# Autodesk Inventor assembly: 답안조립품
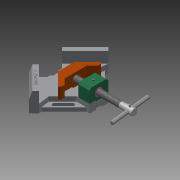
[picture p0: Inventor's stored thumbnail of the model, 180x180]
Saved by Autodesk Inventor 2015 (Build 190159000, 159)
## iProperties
Created: 2020-05
Part Number: 답안조립품
Document SubType Name: Assembly
Designer: now
Author: now
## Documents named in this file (11)
- C:\Users\now\Desktop\700506V1009\답안조립품.iam
- C:\Users\now\Desktop\700506V1009\리드스크류.ipt
- C:\Users\now\Desktop\700506V1009\멈춤나사 M4x5.ipt
- C:\Users\now\Desktop\700506V1009\멈춤나사 M4x10.ipt
- C:\Users\now\Desktop\700506V1009\본체.ipt
- C:\Users\now\Desktop\700506V1009\볼트 M4x16.ipt
- C:\Users\now\Desktop\700506V1009\부시.ipt
- C:\Users\now\Desktop\700506V1009\서포트.ipt
- C:\Users\now\Desktop\700506V1009\조.ipt
- C:\Users\now\Desktop\700506V1009\평행 핀 2.5x24.ipt
- C:\Users\now\Desktop\700506V1009\핸들.ipt
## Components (1 placed, 1 different names)
1. 핸들:1
